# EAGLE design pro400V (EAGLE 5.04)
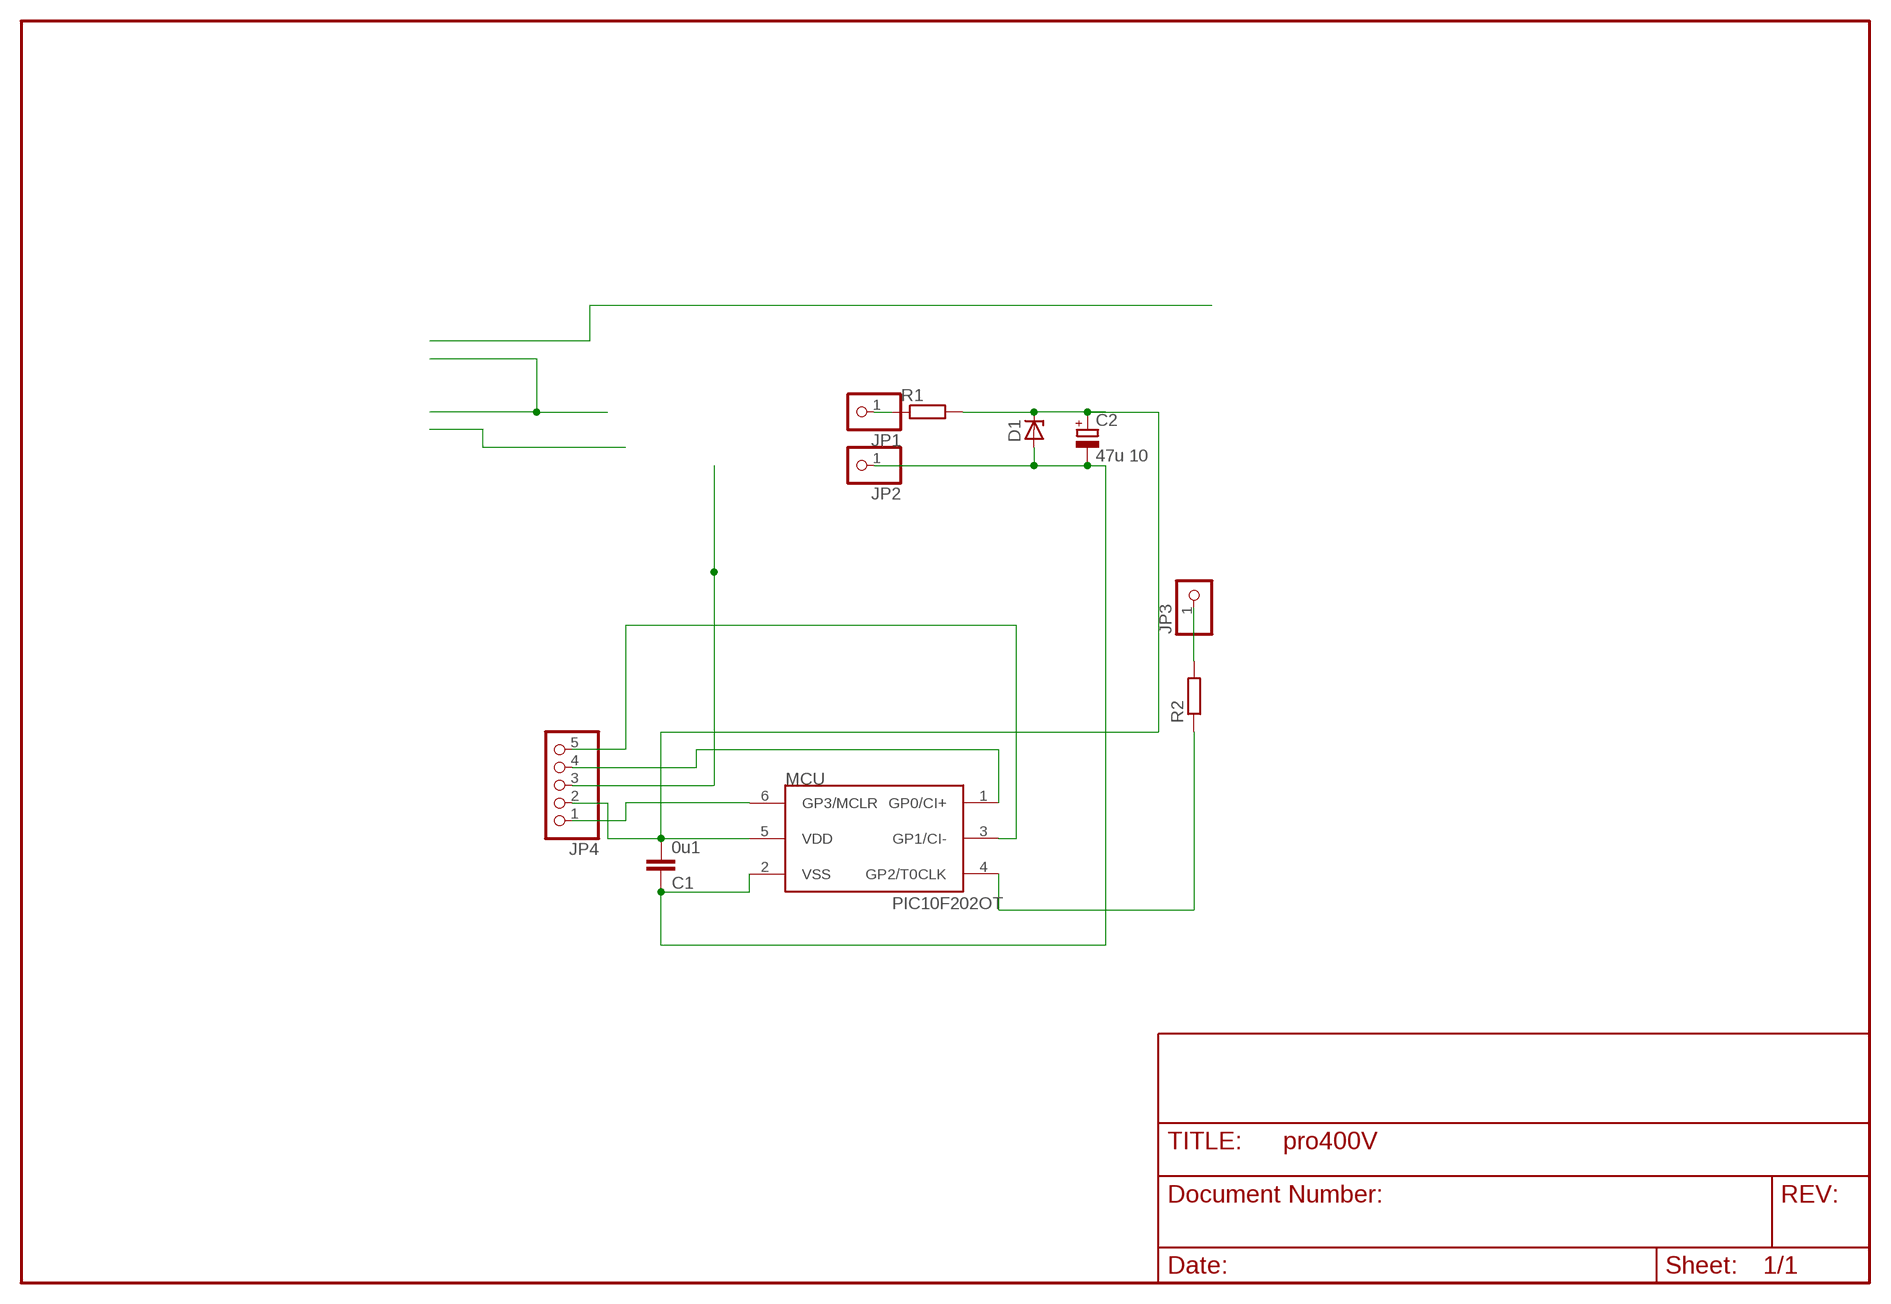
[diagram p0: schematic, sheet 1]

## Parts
C1  0u1  C-EUC0805  [C0805]
C2  47u 10  CPOL-EUE2-5  [E2-5]
D1  ZENER-DIODESOT23  [SOT23]
JP1  PINHD-1X1  [1X01]
JP2  PINHD-1X1  [1X01]
JP3  PINHD-1X1  [1X01]
JP4  PINHD-1X5  [1X05]
MCU  PIC10F202OT  [SOT23-6]
R1  R-EU_R0805  [R0805]
R2  R-EU_R0805  [R0805]

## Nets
GATE: MCU.4(GP2/T0CLK) R2.1
GP0: JP4.4 MCU.1(GP0/CI+)
GP1: JP4.5 MCU.3(GP1/CI-)
GP3: JP4.1 MCU.6(GP3/MCLR)
N$2: C1.1 C2.- D1.1(A) JP2.1 MCU.2(VSS)
N$3: JP1.1 R1.1
N$4: JP3.1 R2.2
VDD: C1.2 C2.+ D1.3(C) JP4.2 MCU.5(VDD) R1.2
VSS: JP4.3

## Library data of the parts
C1 = rcl:C-EU: CAPACITOR, European symbol
C2 = rcl:CPOL-EU: POLARIZED CAPACITOR, European symbol
D1 = diode-1:ZENER-DIODE: Z-Diode
JP1-JP3 = pinhead:PINHD-1X1: PIN HEADER
JP4 = pinhead(2):PINHD-1X5: PIN HEADER
MCU = microchip-3:PIC10F2*: uPC nW 0,25/0,5k Program Flash memory Comparator
R1 R2 = rcl-2:R-EU_: RESISTOR, European symbol

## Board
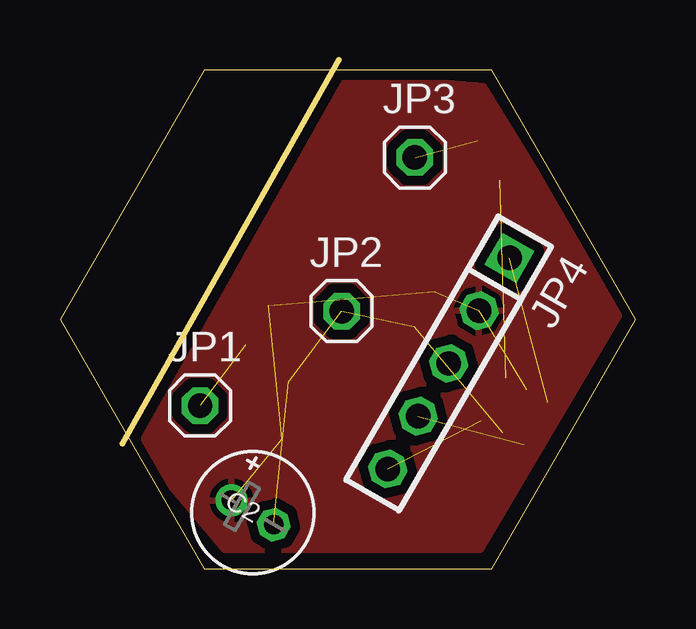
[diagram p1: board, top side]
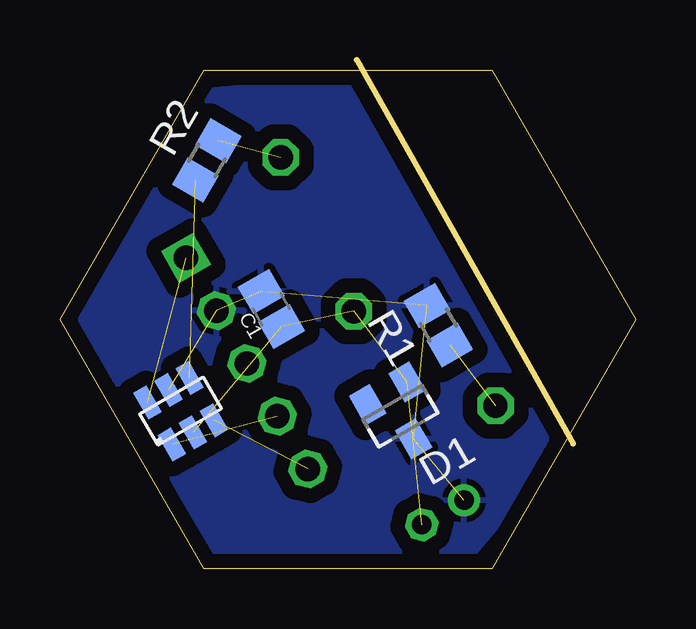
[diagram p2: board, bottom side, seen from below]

Size 24 x 21.21 mm. Coordinates in mm from the lower left corner, seen from the top.
Outline: 11.62,21.21 2.6,5.21
Outline: 6,0 18,0 24,10.39 18,20.78 6,20.78 0,10.39 6,0
Copper layers (1*16): Top 0.035mm / dielectric 1.5mm / Bottom 0.035mm
Design rules "default": minimum track width 10mil, minimum drill 24mil, track to track 8mil, track to pad 8mil, pad to pad 8mil, via to via 8mil, smd to smd 8mil, copper to edge 8mil, drill to drill 8mil, minimum pad ring 10mil, minimum via ring 8mil, stop-mask expansion 4mil, vias tented up to drill 0mil, thermal gap 10mil

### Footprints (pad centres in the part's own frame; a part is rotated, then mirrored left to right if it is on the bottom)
C0805 = smd 1.3 x 1.5: 1 -0.85,0; 2 0.85,0
E2-5 = drill 0.813 pad 1.27 round: + -1.016,0 | drill 0.813 pad 1.27 octagon: - 1.016,0
SOT23 = smd 1 x 1.4: 1 -0.95,-1.1; 2 0.95,-1.1; 3 0,1.1
1X01 = drill 1.016 octagon: 1 0,0
1X05 = drill 1.016 square: 1 -5.08,0 | drill 1.016 octagon: 2 -2.54,0; 3 0,0; 4 2.54,0; 5 5.08,0
SOT23-6 = smd 0.635 x 1.27: 1 -1.016,-1.016; 2 0,-1.016; 3 1.016,-1.016; 4 1.016,1.016; 5 0,1.016; 6 -1.016,1.016
R0805 = smd 1.3 x 1.5: 1 -0.95,0; 2 0.95,0

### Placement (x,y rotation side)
C1  15.19,10.82 120 bottom
C2  8.04,2.34 330 top
D1  9.8,6.36 210 bottom
JP1  5.84,6.79 0 top
JP2  11.75,10.73 0 top
JP3  14.8,17.14 0 top
JP4  16.21,8.55 240 top
MCU  18.97,6.56 30 bottom
R1  8.22,10.15 120 bottom
R2  17.88,17.03 60 bottom

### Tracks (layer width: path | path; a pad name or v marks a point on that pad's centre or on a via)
GATE  (1 unrouted)
GP0  (1 unrouted)
GP1  (1 unrouted)
GP3  (1 unrouted)
N$2  (4 unrouted)
N$3  (1 unrouted)
N$4  (1 unrouted)
VDD  (5 unrouted)
  pour Top (isolate 0.406): 11.75,20.64 17.65,20.13 23.43,10.73 17.53,0.76 6.86,0.76 3.17,5.14 7.11,12.38
  pour Bottom (isolate 0.61): 11.68,20.45 17.59,19.94 23.37,10.54 17.46,0.57 6.79,0.57 3.11,4.95 7.05,12.19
